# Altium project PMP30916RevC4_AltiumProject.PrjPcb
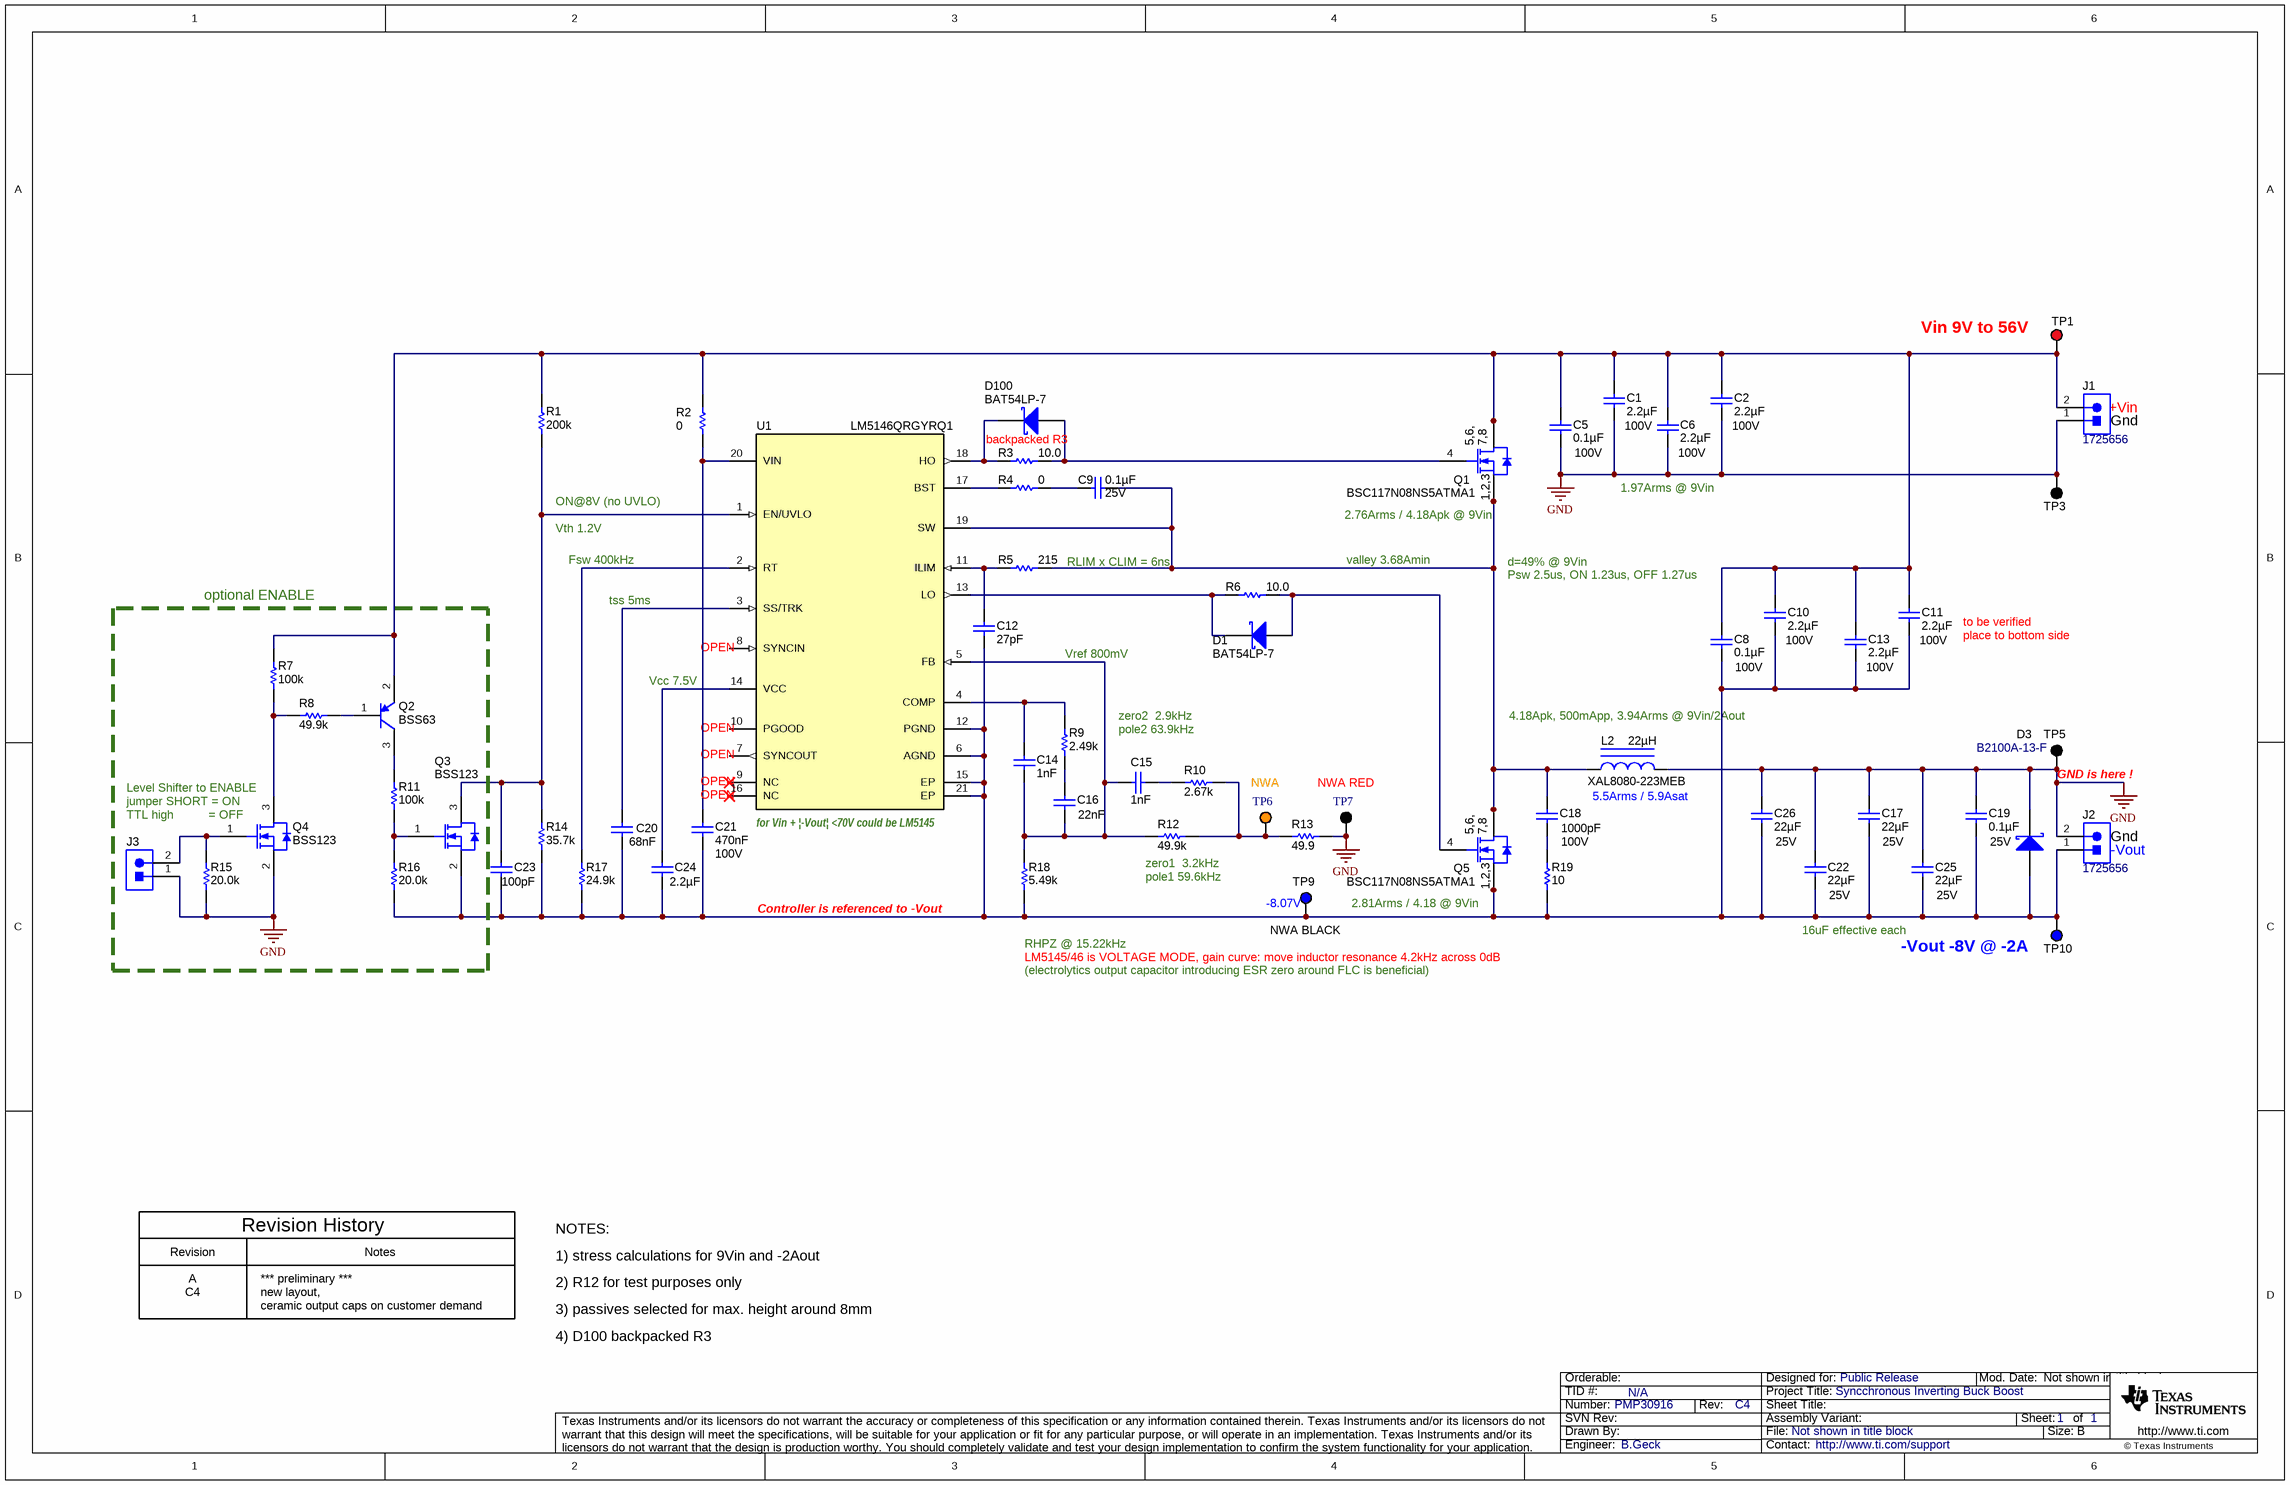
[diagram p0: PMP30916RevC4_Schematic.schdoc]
PCB_Layout: B.Geck; PCB_Rev: C4; PRJ_Customer: Public Release; PRJ_Engineer: B.Geck; PRJ_Number: PMP30916; PRJ_Title: Syncchronous Inverting Buck Boost; SCH_Rev: C4; TechSupport: http://www.ti.com/support; TID: N/A
1 sheet, 62 parts. Net scope: global (net labels, ports and power ports of the same name join across sheets).
Board file: PMP30916RevC4_board.PcbDoc

## Sheet PMP30916RevC4_Schematic.schdoc
size 431 x 279 mm; Date: Not shown in title block; ApprovedBy: Not shown in title block; CheckedBy: Not shown in title block; Author: Not shown in title block; CompanyName: Not shown in title block; Engineer: Not shown in title block; Organization: Not shown in title block; Address1: Not shown in title block; Address2: Not shown in title block; Address3: Not shown in title block; Address4: Not shown in title block; DocumentNumber: 1; Revision: Use project parameter SCH_Rev; SheetNumber: 1; SheetTotal: 1; PageSetup: Record=PageOptions¦CenterHorizontal=True¦CenterVertical=True¦PrintScale=0.70¦XCorrection=1.00¦YCorrection=1.00¦PrintKind=0¦BorderSize=5000000¦LeftOffset=0¦BottomOffset=0¦Orientation=2¦PaperLength=1000¦PaperWidth=1000¦Scale=100¦PaperSource=15¦PrintQuality=600¦MediaType=1¦DitherType=10¦PaperKind=A4¦PrintScaleMode=1

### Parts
C1  ValueDisplayed: 2.2µF  Value2: 100V  [1210_270]  (hidden comment: GRM32ER72A225KA35L)
C2  ValueDisplayed: 2.2µF  Value2: 100V  [1210_270]  (hidden comment: GRM32ER72A225KA35L)
C5  ValueDisplayed: 0.1µF  Value2: 100V  [0603]  (hidden comment: GRM188R72A104KA35D)
C6  ValueDisplayed: 2.2µF  Value2: 100V  [1210_270]  (hidden comment: GRM32ER72A225KA35L)
C8  ValueDisplayed: 0.1µF  Value2: 100V  [0603]  (hidden comment: GRM188R72A104KA35D)
C9  ValueDisplayed: 0.1µF  Value2: 25V  [0603]  (hidden comment: GRM188R71E104KA01D)
C10  ValueDisplayed: 2.2µF  Value2: 100V  [1210_270]  (hidden comment: GRM32ER72A225KA35L)
C11  ValueDisplayed: 2.2µF  Value2: 100V  [1210_270]  (hidden comment: GRM32ER72A225KA35L)
C12  ValueDisplayed: 27pF  [0603]  (hidden comment: GRM1885C1H270JA01D)
C13  ValueDisplayed: 2.2µF  Value2: 100V  [1210_270]  (hidden comment: GRM32ER72A225KA35L)
C14  Cap_F: 1nF  [0603]  (hidden comment: GRM188R71H102KA01D)
C15  Cap_F: 1nF  [0603]  (hidden comment: GRM188R71H102KA01D)
C16  ValueDisplayed: 22nF  [0603]  (hidden comment: GRM188R71C223KA01D)
C17  ValueDisplayed: 22µF  Value2: 25V  [1210_270]  (hidden comment: GRM32ER71E226KE15L)
C18  VDC_V: 100V  ValueDisplayed: 1000pF  [0603]  (hidden comment: C1608X7R2A102K080AA)
C19  ValueDisplayed: 0.1µF  Value2: 25V  [0603]  (hidden comment: GRM188R71E104KA01D)
C20  ValueDisplayed: 68nF  [0603]  (hidden comment: GRM188R71C683KA01D)
C21  Cap_F: 470nF  VDC_V: 100V  [0805_HV]  (hidden comment: GRM21BR72A474KA73L)
C22  ValueDisplayed: 22µF  Value2: 25V  [1210_270]  (hidden comment: GRM32ER71E226KE15L)
C23  ValueDisplayed: 100pF  [0603]  (hidden comment: GRM1885C1H101JA01D)
C24  ValueDisplayed: 2.2µF  [0805_HV]  (hidden comment: GCM21BR71E225KA73L)
C25  ValueDisplayed: 22µF  Value2: 25V  [1210_270]  (hidden comment: GRM32ER71E226KE15L)
C26  ValueDisplayed: 22µF  Value2: 25V  [1210_270]  (hidden comment: GRM32ER71E226KE15L)
D1  BAT54LP-7  [X1-DFN1006-2]
D3  B2100A-13-F  [SMA]
D100  BAT54LP-7  [X1-DFN1006-2]
J1  1725656  [CONN_1725656]
J2  1725656  [CONN_1725656]
J3  PEC02SAAN  [CONN_PEC02SAAN]  (value not drawn)
L2  XAL8080-223MEB  ValueDisplayed: 22µH  [XAL8080]
Q1  BSC117N08NS5ATMA1  [PG-TDSON-8]
Q2  BSS63  [SOT-23]
Q3  BSS123  [SOT-23]
Q4  BSS123  [SOT-23]
Q5  BSC117N08NS5ATMA1  [PG-TDSON-8]
R1  ValueDisplayed: 200k  [0603]  (hidden comment: CRCW0603200KFKEA)
R2  ValueDisplayed: 0  [0603]  (hidden comment: RMCF0603ZT0R00)
R3  ValueDisplayed: 10.0  [0603]  (hidden comment: CRCW060310R0FKEA)
R4  ValueDisplayed: 0  [0603]  (hidden comment: RMCF0603ZT0R00)
R5  ValueDisplayed: 215  [0603]  (hidden comment: CRCW0603215RFKEA)
R6  ValueDisplayed: 10.0  [0603]  (hidden comment: CRCW060310R0FKEA)
R7  ValueDisplayed: 100k  [0603]  (hidden comment: CRCW0603100KFKEA)
R8  ValueDisplayed: 49.9k  [0603]  (hidden comment: CRCW060349K9FKEA)
R9  ValueDisplayed: 2.49k  [0603]  (hidden comment: CRCW06032K49FKEA)
R10  ValueDisplayed: 2.67k  [0603]  (hidden comment: CRCW06032K67FKEA)
R11  ValueDisplayed: 100k  [0603]  (hidden comment: CRCW0603100KFKEA)
R12  ValueDisplayed: 49.9k  [0603]  (hidden comment: CRCW060349K9FKEA)
R13  ValueDisplayed: 49.9  [0603]  (hidden comment: RC0603FR-0749R9L)
R14  ValueDisplayed: 35.7k  [0603]  (hidden comment: CRCW060335K7FKEA)
R15  ValueDisplayed: 20.0k  [0603]  (hidden comment: CRCW060320K0FKEA)
R16  ValueDisplayed: 20.0k  [0603]  (hidden comment: CRCW060320K0FKEA)
R17  ValueDisplayed: 24.9k  [0603]  (hidden comment: CRCW060324K9FKEA)
R18  ValueDisplayed: 5.49k  [0603]  (hidden comment: CRCW06035K49FKEA)
R19  ValueDisplayed: 10  [1206]  (hidden comment: CRCW120610R0JNEA)
TP1  5010  [Keystone5010]  (value not drawn)
TP3  5011  [Keystone5011]  (value not drawn)
TP5  5011  [Keystone5011]  (value not drawn)
TP6  5003  [Keystone5003]  (value not drawn)
TP7  5001  [Keystone5001]  (value not drawn)
TP9  5117  [Keystone5117]  (value not drawn)
TP10  5127  [Keystone5127]  (value not drawn)
U1  LM5146QRGYRQ1  [RGY0020B]

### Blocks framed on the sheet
optional ENABLE: J3 Q2-Q4 R7 R8 R11 R15 R16

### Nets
GND: C1.2 C2.2 C5.2 C6.2 C17.2 C19.1 C22.2 C25.2 C26.2 D3.1(K) J1.1 J2.2 J3.1 L2.2 Q4.2(S) R13.2 R15.1 TP3.1 TP5.1 TP7.1
NetC1_1: C1.1 C2.1 C5.1 C6.1 C8.1 C10.1 C11.1 C13.1 J1.2 Q1.5(D) Q1.6(D) Q1.7(D) Q1.8(D) Q1.9(D) Q2.2(E) R1.2 R2.2 R7.2 TP1.1
NetC8_2: C8.2 C10.2 C11.2 C12.2 C13.2 C17.1 C19.2 C20.2 C21.2 C22.1 C23.2 C24.2 C25.1 C26.1 D3.2(A) J2.1 Q3.2(S) Q5.1(S) Q5.2(S) Q5.3(S) R14.1 R16.1 R17.1 R18.1 R19.1 TP9.1 TP10.1 U1.6(AGND) U1.12(PGND) U1.15(EP) U1.21(EP)
NetC9_1: C9.1 R4.2
NetC9_2: C9.2 C18.1 L2.1 Q1.1(S) Q1.2(S) Q1.3(S) Q5.5(D) Q5.6(D) Q5.7(D) Q5.8(D) Q5.9(D) R5.2 U1.19(SW)
NetC12_1: C12.1 R5.1 U1.11(ILIM)
NetC14_1: C14.1 R9.2 U1.4(COMP)
NetC14_2: C14.2 C15.2 C16.2 R12.1 R18.2 U1.5(FB)
NetC15_1: C15.1 R10.1
NetC16_1: C16.1 R9.1
NetC18_2: C18.2 R19.2
NetC20_1: C20.1 U1.3(SS/TRK)
NetC21_1: C21.1 R2.1 U1.20(VIN)
NetC23_1: C23.1 Q3.3(D) R1.1 R14.2 U1.1(EN/UVLO)
NetC24_1: C24.1 U1.14(VCC)
NetD1_1: D1.1(K) R6.1 U1.13(LO)
NetD1_2: D1.2(A) Q5.4(G) R6.2
NetD100_1: D100.1(K) R3.1 U1.18(HO)
NetD100_2: D100.2(A) Q1.4(G) R3.2
NetJ3_2: J3.2 Q4.1(G) R15.2
NetQ2_1: Q2.1(B) R8.2
NetQ2_3: Q2.3(C) R11.2
NetQ3_1: Q3.1(G) R11.1 R16.2
NetQ4_3: Q4.3(D) R7.1 R8.1
NetR4_1: R4.1 U1.17(BST)
NetR10_2: R10.2 R12.2 R13.1 TP6.1
NetR17_2: R17.2 U1.2(RT)

Not connected (* = marked no-connect by the designer): U1 7(SYNCOUT) 8(SYNCIN) 9(NC)* 10(PGOOD) 16(NC)*

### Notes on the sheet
- (near TP1) Vin 9V to 56V
- (near J1) Gnd
- (near J1) +Vin
- ON@8V (no UVLO)
- backpacked R3
- 1.97Arms @ 9Vin
- Vth 1.2V
- Fsw 400kHz
- (near R5) RLIM x CLIM = 6ns
- valley 3.68Amin
- (near Q1) 2.76Arms / 4.18Apk @ 9Vin
- d=49% @ 9Vin
- Psw 2.5us, ON 1.23us, OFF 1.27us
- tss 5ms
- to be verified
- place to bottom side
- Vcc 7.5V
- (near U1) OPEN
- Vref 800mV
- zero2  2.9kHz
- pole2 63.9kHz
- 4.18Apk, 500mApp, 3.94Arms @ 9Vin/2Aout
- (near Q4) Level Shifter to ENABLE
- (near Q4) jumper SHORT = ON
- (near Q4) TTL high          = OFF
- OPEN
- (near U1) for Vin + ¦-Vout¦ <70V could be LM5145
- NWA
- NWA RED
- (near L2) 5.5Arms / 5.9Asat
- (near TP5) GND is here !
- (near J2) Gnd
- (near R12) zero1  3.2kHz
- (near R12) pole1 59.6kHz
- (near TP9) -8.07V
- 2.81Arms / 4.18 @ 9Vin
- (near J2) -Vout
- Controller is referenced to -Vout
- (near R18) RHPZ @ 15.22kHz
- LM5145/46 is VOLTAGE MODE, gain curve: move inductor resonance 4.2kHz across 0dB
- (electrolytics output capacitor introducing ESR zero around FLC is beneficial)
- (near TP9) NWA BLACK
- 16uF effective each
- (near TP10) -Vout -8V @ -2A
- Revision History
- NOTES:
- Revision
- A
- C4
- *** preliminary ***
- new layout,
- ceramic output caps on customer demand
- Notes
- 1) stress calculations for 9Vin and -2Aout
- 2) R12 for test purposes only
- 3) passives selected for max. height around 8mm
- 4) D100 backpacked R3

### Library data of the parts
C1 C2 C6 C10 C11 C13 = GRM32ER72A225KA35L: CAP, CERM, 2.2 µF, 100 V,+/- 10%, X7R, 1210; Manufacturer: MuRata; Polarized: N; CompType: Capacitor; Value: 2.2uF; U/M: EA; Cap_F: 0.0000022; Tolerance_%: 10; ESR_ohm: 0.007; Value1: 0.007 ohm; VDC_V: 100; IRMS_A: 4.4; TaMin_C: -55; TaMax_C: 125; Cap_Case: 1210; SizeArea_mm2: 8; SizeAreaWB_mm2: 14.7; SizeX_mm: 3.2; SizeY_mm: 2.5; SizeZ_mm: 2.7; AEC Category: Q200; Green_Lifecycle: Active; Green_REACh: Passed
C5 C8 = GRM188R72A104KA35D: CAP, CERM, 0.1 µF, 100 V,+/- 10%, X7R, 0603; Manufacturer: MuRata; Polarized: N; CompType: Capacitor; Value: 0.1uF; U/M: EA; Cap_F: 0.0000001; Tolerance_%: 10; VDC_V: 100; TaMin_C: -55; TaMax_C: 125; SizeArea_mm2: 1.28; SizeAreaWB_mm2: 4.68; SizeX_mm: 1.6; SizeY_mm: 0.8; SizeZ_mm: 1; AEC Category: Q200; Green_Lifecycle: Active; Green_REACh: Passed
C9 C19 = GRM188R71E104KA01D: CAP, CERM, 0.1 µF, 25 V,+/- 10%, X7R, 0603; Manufacturer: MuRata; Polarized: N; CompType: Capacitor; Value: 0.1uF; U/M: EA; Cap_F: 0.0000001; Tolerance_%: 10; VDC_V: 25; TaMin_C: -55; TaMax_C: 125; SizeArea_mm2: 1.28; SizeAreaWB_mm2: 4.68; SizeX_mm: 1.6; SizeY_mm: 0.8; SizeZ_mm: 1; AEC Category: Q200; Green_Lifecycle: Active; Green_REACh: Passed
C12 = GRM1885C1H270JA01D: CAP, CERM, 27 pF, 50 V,+/- 5%, C0G/NP0, 0603; Manufacturer: MuRata; Polarized: N; CompType: Capacitor; Value: 27pF; U/M: EA; Cap_F: 0.000000000027; Tolerance_%: 5; VDC_V: 50; Value2: 50V; TaMin_C: -55; TaMax_C: 125; SizeArea_mm2: 1.28; SizeAreaWB_mm2: 4.68; SizeX_mm: 1.6; SizeY_mm: 0.8; SizeZ_mm: 1; AEC Category: Q200; Green_Lifecycle: Active; Green_REACh: Passed
C14 C15 = CMP-0007432-5: CAP, CERM, 1000 pF, 50 V, +/- 10%, X7R, 0603; Manufacturer: MuRata; TaMin_C: -55°C; Polarized: N; SizeAreaWB_mm2: 4.68; Value1: Unknown; U/M: EA; Value: 1000pF; TaMax_C: 125°C; SizeZ_mm: 1; SizeX_mm: 1.6; SizeY_mm: 0.8; Value2: 50V; SizeArea_mm2: 1.28; AEC Category: Q200
C16 = GRM188R71C223KA01D: CAP, CERM, 0.022 µF, 16 V,+/- 10%, X7R, 0603; Manufacturer: MuRata; Polarized: N; CompType: Capacitor; Value: 0.022uF; U/M: EA; Cap_F: 0.000000022; Tolerance_%: 10; VDC_V: 16; Value2: 16V; TaMin_C: -55; TaMax_C: 125; SizeArea_mm2: 1.28; SizeAreaWB_mm2: 4.68; SizeX_mm: 1.6; SizeY_mm: 0.8; SizeZ_mm: 1; AEC Category: Q200; Green_Lifecycle: Active; Green_REACh: Passed
C17 C22 C25 C26 = GRM32ER71E226KE15L: CAP, CERM, 22 µF, 25 V,+/- 10%, X7R, 1210; Manufacturer: MuRata; Polarized: N; CompType: Capacitor; Value: 22uF; U/M: EA; Cap_F: 0.000022; Tolerance_%: 10; ESR_ohm: 0.002334; Value1: 0.002334 ohm; VDC_V: 25; IRMS_A: 3.832999; TaMin_C: -55; TaMax_C: 125; Cap_Case: 1210; SizeArea_mm2: 8; SizeAreaWB_mm2: 14.7; SizeX_mm: 3.2; SizeY_mm: 2.5; SizeZ_mm: 2.7; AEC Category: Q200; Green_Lifecycle: Active; Green_REACh: Passed
C18 = CMP-0007053-4: CAP, CERM, 1000 pF, 100 V, +/- 10%, X7R, 0603; Manufacturer: TDK; TaMin_C: -55°C; Polarized: N; SizeAreaWB_mm2: 4.68; Value1: Unknown; U/M: EA; Value: 1000pF; TaMax_C: 125°C; SizeZ_mm: 1; SizeX_mm: 1.6; SizeY_mm: 0.8; SizeArea_mm2: 1.28; Cap_F: 1nF; AEC Category: Q200
C20 = CMP-0007400-1: CAP, CERM, 0.068 uF, 16 V, +/- 10%, X7R, 0603; Manufacturer: MuRata; TaMin_C: -55°C; Polarized: N; SizeAreaWB_mm2: 4.68; Value1: Unknown; U/M: EA; TaMax_C: 125°C; SizeZ_mm: 1; SizeX_mm: 1.6; SizeY_mm: 0.8; Value2: 16V; SizeArea_mm2: 1.28; AEC Category: Q200
C21 = CMP-0008374-2: CAP, CERM, 0.47 uF, 100 V, +/- 10%, X7R, 0805; Manufacturer: MuRata; TaMin_C: -55°C; Polarized: N; SizeAreaWB_mm2: 6.75; Value1: Unknown; U/M: EA; Value: 0.47uF; TaMax_C: 125°C; SizeZ_mm: 1.45; SizeX_mm: 2; SizeY_mm: 1.25; Cap_Case: 0805; SizeArea_mm2: 2.5; AEC Category: Q200
C23 = GRM1885C1H101JA01D: CAP, CERM, 100 pF, 50 V,+/- 5%, C0G/NP0, 0603; Manufacturer: MuRata; Polarized: N; CompType: Capacitor; Value: 100pF; U/M: EA; Cap_F: 0.0000000001; Tolerance_%: 5; VDC_V: 50; Value2: 50V; TaMin_C: -55; TaMax_C: 125; SizeArea_mm2: 1.28; SizeAreaWB_mm2: 4.68; SizeX_mm: 1.6; SizeY_mm: 0.8; SizeZ_mm: 1; AEC Category: Q200; Green_Lifecycle: Active; Green_REACh: Passed
C24 = CMP-0083622-1: CAP, CERM, 2.2 µF, 25 V,+/- 10%, X7R, AEC-Q200 Grade 1, 0805; Manufacturer: MuRata; TaMin_C: -55°C; Polarized: N; SizeAreaWB_mm2: 6.75; U/M: EA; Value: 2.2uF; TaMax_C: 125°C; SizeZ_mm: 1.45; SizeX_mm: 2; SizeY_mm: 1.25; Cap_Case: 0805; Value2: 25V; SizeArea_mm2: 2.5; AEC Qualified: Y; AEC Grade: 1; AEC Category: Q200
D1 D100 = CMP-0076931-2: Diode, Schottky, 30 V, 0.2 A, 1.00x0.50x0.60mm; Manufacturer: Diodes Inc.; SizeArea_mm2: 0.6; Green_Lifecycle: Not Set; Io_A: 200mA; Value2: 1V; Green_REACh: Incomplete; Value1: 0.2A; Vr_V: 30V; AEC Category: Q101; SizeAreaWB_mm2: 3.2; Value: 30V; SizeX_mm: 1.0; SizeZ_mm: 0.53
D3 = CMP-0081099-2: Diode, Schottky, 100 V, 2 A, SMA; Manufacturer: Diodes Inc.; SizeZ_mm: 2.87; SizeX_mm: 5.59; AEC Qualified: N; Value2: 0.79V; SizeArea_mm2: 16.3228; Vf_V: 790mV; AEC Category: Q101; TJmax_C: 125°C; Vr_V: 100V; Value: 100V; Io_A: 2A; SizeAreaWB_mm2: 37.3428; SizeY_mm: 2.92
J1 J2 = CMP-0055479-2: Terminal Block, 100mil, 2x1, 6A, 63V, TH; Manufacturer: Phoenix Contact; Green_REACh: Incomplete; CNHeader: FALSE; CT: TRUE; Green_Lifecycle: Not Set
J3 = PEC02SAAN: Header, 100mil, 2x1, Tin, TH; Manufacturer: Sullins Connector Solutions; SymbolCreator: a0412235; Pitch_mm: 2.54; Gender: Male; Shrouded: N; Row_Count: 1; Current_A: 3; Voltage_V: 1800; Cert_UL: Y; Green_Lifecycle: Not Set; Green_REACh: Incomplete
L2 = XAL8080-103MEB: Inductor, Shielded, Composite, 22 µH, 5.9 A, 0.033 ohm, SMD; Manufacturer: Coilcraft; Value: 22uH; Ind_H: 22.0E-6; Imax_A: 7.5; Irms: 7.5A @ 40C rise; Isat: 6A @ 30% inductance drop; DCR_ohm: 0.033; Value2: 5.9A; SizeAreaWB_mm2: 107.06; SizeArea_mm2: 69.66; SizeX_mm: 8.1; SizeY_mm: 8.6; SizeZ_mm: 8; AEC Category: Q200; AEC Qualified: N; Green_Lifecycle: Not Set; Green_REACh: Incomplete
Q1 Q5 = BSC117N08NS5ATMA1: MOSFET, N-CH, 80 V, 49 A, PG-TDSON-8; Manufacturer: Infineon Technologies; Alternate Manufacturer: None; U/M: EA; ChType: N; Value: 80V; VdsMax_V: 80; Value1: ? ohm; Value2: 15 nC; QgTyp_nC: 15; Vgs_V: 20; IdsMax_A: 49; SizeAreaWB_mm2: 55.131; SizeArea_mm2: 29.351; SizeX_mm: 5.99; SizeY_mm: 4.9; SizeZ_mm: 1.12; AEC Category: Q101; Green_Lifecycle: Not Set; Green_REACh: Incomplete
Q2 = BSS63, Fairchild Semiconductor: Transistor, PNP, 100 V, 0.2 A, SOT-23; CompType: BJT; PNP: 1; NPN: 0; Vceo_V: 100; Vcesat1_V: 0.25; Value: 100 V; IcRated_A: 0.2; Value1: 0.2 A; TaMin_C: -55; TaMax_C: 150; SizeAreaWB_mm2: 14; SizeArea_mm2: 7.5; SizeX_mm: 2.5; SizeY_mm: 3; SizeZ_mm: 1.1; U/M: EA; AEC Category: Q101; AEC Qualified: N
Q3 Q4 = BSS123: MOSFET, N-CH, 100 V, 0.17 A, SOT-23; Manufacturer: Fairchild Semiconductor; Alternate Manufacturer: None; U/M: EA; ChType: N; Value: 100V; VdsMax_V: 100; Value1: 10 ohm; Rdson45_ohm: 10; Value2: 1.8 nC; QgTyp_nC: 1.8; Vgs_V: 20; IdsMax_A: 0.17; SizeAreaWB_mm2: 14; SizeArea_mm2: 7.5; SizeX_mm: 2.5; SizeY_mm: 3; SizeZ_mm: 1.1; AEC Category: Q101; Green_Lifecycle: Active; Green_REACh: Passed
R1 = CRCW0603200KFKEA: RES, 200 k, 1%, 0.1 W, 0603; Manufacturer: Vishay-Dale; CompType: Resistor; Value: 200k; Res_ohm: 200000; Tolerance_%: 1; Power_W: 0.1; Value2: 0.1W; VDC_V: 75; TempCo: 100 ppm/C; SizeArea_mm2: 1.28; SizeX_mm: 1.6; SizeY_mm: 0.8; EIA_Code: E96; U/M: EA; AEC Category: Q200; Green_Lifecycle: Active; Green_REACh: Passed
R2 R4 = CMP-0023343-1: RES, 0, 1%, 0.1 W, AEC-Q200 Grade 0, 0603; Manufacturer: Stackpole Electronics Inc; Power_W: 100mW; TempCo: ppm/C; U/M: EA; Value: 0; SizeX_mm: 1.6; SizeY_mm: 0.8; SizeZ_mm: 1; Value2: 0.1W; SizeArea_mm2: 1.28; AEC Qualified: Y; AEC Category: Q200
R3 R6 = CRCW060310R0FKEA: RES, 10.0, 1%, 0.1 W, 0603; Manufacturer: Vishay-Dale; CompType: Resistor; Value: 10.0; Res_ohm: 10; Value_Code: 10R0; Tolerance_%: 1; Power_W: 0.1; Value2: 0.1W; VDC_V: 75; TempCo: 100 ppm/C; SizeArea_mm2: 1.28; SizeX_mm: 1.6; SizeY_mm: 0.8; EIA_Code: E96; U/M: EA; AEC Category: Q200; Green_Lifecycle: Active; Green_REACh: Passed
R5 = CRCW0603215RFKEA: RES, 215, 1%, 0.1 W, 0603; Manufacturer: Vishay-Dale; CompType: Resistor; Value: 215; Value_Code: 215R; Tolerance_%: 1; Power_W: 0.1; Value2: 0.1W; VDC_V: 75; TempCo: 100 ppm/C; SizeArea_mm2: 1.28; SizeX_mm: 1.6; SizeY_mm: 0.8; EIA_Code: E96; U/M: EA; AEC Category: Q200
R7 R11 = CRCW0603100KFKEA: RES, 100 k, 1%, 0.1 W, 0603; Manufacturer: Vishay-Dale; CompType: Resistor; Value: 100k; Res_ohm: 100000; Tolerance_%: 1; Power_W: 0.1; Value2: 0.1W; VDC_V: 75; TempCo: 100 ppm/C; SizeArea_mm2: 1.28; SizeX_mm: 1.6; SizeY_mm: 0.8; EIA_Code: E96; U/M: EA; AEC Category: Q200; Green_Lifecycle: Active; Green_REACh: Passed
R8 R12 = CRCW060349K9FKEA: RES, 49.9 k, 1%, 0.1 W, 0603; Manufacturer: Vishay-Dale; CompType: Resistor; Value: 49.9k; Res_ohm: 49900; Value_Code: 49k9; Tolerance_%: 1; Power_W: 0.1; Value2: 0.1W; VDC_V: 75; TempCo: 100 ppm/C; SizeArea_mm2: 1.28; SizeX_mm: 1.6; SizeY_mm: 0.8; EIA_Code: E96; U/M: EA; AEC Category: Q200; Green_Lifecycle: Active; Green_REACh: Passed
R9 = CRCW06032K49FKEA: RES, 2.49 k, 1%, 0.1 W, 0603; Manufacturer: Vishay-Dale; CompType: Resistor; Value: 2.49k; Res_ohm: 2490; Value_Code: 2k49; Tolerance_%: 1; Power_W: 0.1; Value2: 0.1W; VDC_V: 75; TempCo: 100 ppm/C; SizeArea_mm2: 1.28; SizeX_mm: 1.6; SizeY_mm: 0.8; EIA_Code: E96; U/M: EA; AEC Category: Q200; Green_Lifecycle: Active; Green_REACh: Passed
R10 = CMP-0022280-4: RES, 2.67 k, 1%, 0.1 W, AEC-Q200 Grade 0, 0603; Manufacturer: Vishay-Dale; Power_W: 100mW; TempCo: 100 ppm/C; Value_Code: 2k67; Value: 2.67k; EIA_Code: E96; SizeX_mm: 1.6; SizeY_mm: 0.8; SizeZ_mm: 1; Value2: 0.1W; SizeArea_mm2: 1.28; AEC Qualified: Y; VDC_V: 75V; AEC Category: Q200; AEC Grade: 0
R13 = CMP-0023143-5: RES, 49.9, 1%, 0.1 W, 0603; Manufacturer: Yageo; Power_W: 100mW; TempCo: 100 ppm/C; Value_Code: 49R9; Value: 49.9; EIA_Code: E96; SizeX_mm: 1.6; SizeY_mm: 0.8; SizeZ_mm: 1; Value2: 0.1W; SizeArea_mm2: 1.28; AEC Qualified: N; VDC_V: 75V; AEC Category: Q200; SizeAreaWB_mm2: 4.68
R14 = CRCW060335K7FKEA: RES, 35.7 k, 1%, 0.1 W, 0603; Manufacturer: Vishay-Dale; CompType: Resistor; Value: 35.7k; Res_ohm: 35700; Value_Code: 35k7; Tolerance_%: 1; Power_W: 0.1; Value2: 0.1W; VDC_V: 75; TempCo: 100 ppm/C; SizeArea_mm2: 1.28; SizeX_mm: 1.6; SizeY_mm: 0.8; EIA_Code: E96; U/M: EA; AEC Category: Q200; Green_Lifecycle: Active; Green_REACh: Passed
R15 R16 = CRCW060320K0FKEA: RES, 20.0 k, 1%, 0.1 W, 0603; Manufacturer: Vishay-Dale; CompType: Resistor; Value: 20.0k; Res_ohm: 20000; Value_Code: 20k0; Tolerance_%: 1; Power_W: 0.1; Value2: 0.1W; VDC_V: 75; TempCo: 100 ppm/C; SizeArea_mm2: 1.28; SizeX_mm: 1.6; SizeY_mm: 0.8; EIA_Code: E96; U/M: EA; AEC Category: Q200; Green_Lifecycle: Active; Green_REACh: Passed
R17 = CRCW060324K9FKEA: RES, 24.9 k, 1%, 0.1 W, 0603; Manufacturer: Vishay-Dale; CompType: Resistor; Value: 24.9k; Res_ohm: 24900; Value_Code: 24k9; Tolerance_%: 1; Power_W: 0.1; Value2: 0.1W; VDC_V: 75; TempCo: 100 ppm/C; SizeArea_mm2: 1.28; SizeX_mm: 1.6; SizeY_mm: 0.8; EIA_Code: E96; U/M: EA; AEC Category: Q200; Green_Lifecycle: Active; Green_REACh: Passed
R18 = CRCW06035K49FKEA: RES, 5.49 k, 1%, 0.1 W, 0603; Manufacturer: Vishay-Dale; CompType: Resistor; Value: 5.49k; Res_ohm: 5490; Value_Code: 5k49; Tolerance_%: 1; Power_W: 0.1; Value2: 0.1W; VDC_V: 75; TempCo: 100 ppm/C; SizeArea_mm2: 1.28; SizeX_mm: 1.6; SizeY_mm: 0.8; EIA_Code: E96; U/M: EA; AEC Category: Q200; Green_Lifecycle: Active; Green_REACh: Passed
R19 = CRCW120610R0JNEA: RES, 10, 5%, 0.25 W, 1206; Manufacturer: Vishay-Dale; CompType: Resistor; Value: 10; Value_Code: 10R0; Tolerance_%: 5; Power_W: 0.25; Value2: 0.25W; VDC_V: 200; TempCo: 200 ppm/C; SizeArea_mm2: 5.12; SizeX_mm: 3.2; SizeY_mm: 1.6; SizeZ_mm: 1.35; EIA_Code: E24; U/M: EA; AEC Category: Q200
TP1 = CMP-0055147-1: Test Point, Multipurpose, Red, TH; Manufacturer: Keystone; CNHeader: FALSE; Green_Lifecycle: Active; Green_REACh: Passed; ContactFinish: Silver; CT: TRUE
TP3 TP5 = CMP-0055148-1: Test Point, Multipurpose, Black, TH; Manufacturer: Keystone; CNHeader: FALSE; Green_Lifecycle: Active; Green_REACh: Passed; ContactFinish: Silver; CT: TRUE
TP6 = CMP-0055140-1: Test Point, Miniature, Orange, TH; Manufacturer: Keystone; CNHeader: FALSE; ContactFinish: Silver; CT: TRUE; Green_Lifecycle: Active; Green_REACh: Passed
TP7 = CMP-0055138-1: Test Point, Miniature, Black, TH; Manufacturer: Keystone; CNHeader: FALSE; ContactFinish: Silver; CT: TRUE; Green_Lifecycle: Active; Green_REACh: Passed
TP9 = 5117: Test Point, Miniature, Blue, TH; Manufacturer: Keystone; CompType: Test Point Loop; U/M: EA; ContactFinish: Silver; Green_Lifecycle: Active; Green_REACh: Passed
TP10 = CMP-0055156-1: Test Point, Multipurpose, Blue, TH; Manufacturer: Keystone; CNHeader: FALSE; Green_Lifecycle: Active; Green_REACh: Passed; ContactFinish: Silver; CT: TRUE
U1 = CMP-0081848-1: 5.5-V to 100-V Synchronous Buck Controller With Wide Duty Cycle Range, RGY0020B (VQFN-20); Alternate PartNumber: LM5146QRGYTQ1; Alternate Manufacturer: Texas Instruments; SizeAreaWB_mm2: 24.75; SizeZ_mm: 1; SizeX_mm: 3.5; SizeY_mm: 4.5; SizeArea_mm2: 15.75; CompType: IC; AEC Qualified: Y; AEC Category: Q200

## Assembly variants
synch: all parts fitted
